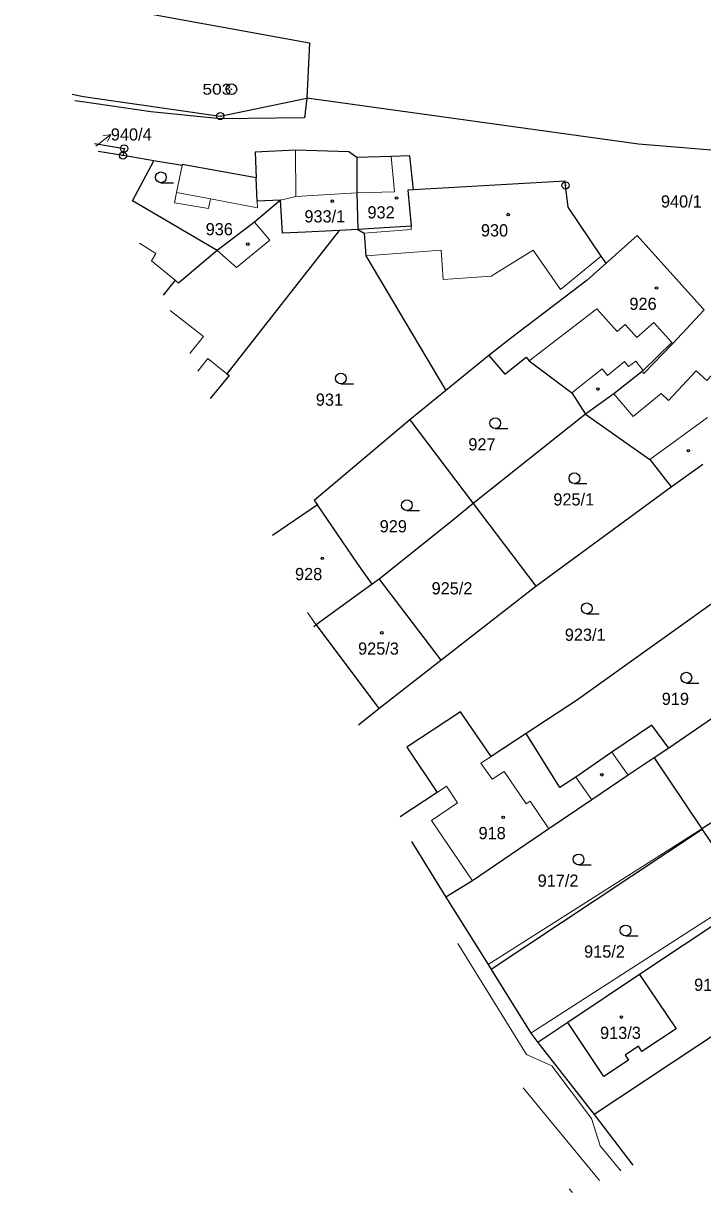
# Model space of a CAD drawing. Extents: x -546984 to -546090, y -1194931 to -1194069.
# Drawn here: x -546957.6 to -546863, y -1194931.4 to -1194768.4 of the extents above; entities that cross this region are included whole.
import ezdxf
from ezdxf.enums import TextEntityAlignment as Align

# ---------------------------------------------------------------- set-up
doc = ezdxf.new("R2010")
doc.units = 0
doc.header["$LTSCALE"] = 0.68
for name, color, linetype, lineweight in [('1', 7, 'Continuous', 25), ('3', 7, 'Continuous', 25), ('4', 7, 'Continuous', 13), ('5', 7, 'Continuous', 25), ('7', 7, 'Continuous', 13), ('8', 7, 'Continuous', 25)]:
    doc.layers.add(name, color=color, linetype=linetype, lineweight=lineweight)
doc.layers.add('2', color=7, linetype='Continuous')

msp = doc.modelspace()

# ---------------------------------------------------------------- linework, layer by layer
at = {"layer": '1'}
for p, q in [((-546911.03, -1194797.1), (-546913.62, -1194797.22)), ((-546892.79, -1194814.67), (-546898.76, -1194819.54)), ((-546867.38, -1194832.99), (-546862.93, -1194829.81)), ((-546886.24, -1194846.83), (-546867.38, -1194832.99)), ((-546916.66, -1194835.51), (-546922.94, -1194839.751)), ((-546908.06, -1194845.85), (-546909.05, -1194846.57)), ((-546908.06, -1194845.85), (-546899.47, -1194857.17)), ((-546899.47, -1194857.17), (-546886.24, -1194846.83)), ((-546916.86, -1194852.24), (-546917.155, -1194852.494)), ((-546916.86, -1194852.24), (-546908.09, -1194863.91)), ((-546908.09, -1194863.91), (-546899.47, -1194857.17)), ((-546910.956, -1194866.15), (-546908.09, -1194863.91)), ((-546869.72, -1194870.76), (-546863.06, -1194880.69)), ((-546863.02, -1194880.74), (-546892.43, -1194900.27)), ((-546903.561, -1194882.442), (-546898.78, -1194890.19)), ((-546856.33, -1194890.73), (-546871.76, -1194900.97)), ((-546871.76, -1194900.97), (-546881.77, -1194907.68)), ((-546881.087, -1194931.397), (-546881.569, -1194930.888))]:
    msp.add_line(p, q, dxfattribs=at)
for points in [[(-546957.649, -1194763.287), (-546946.96, -1194765.76), (-546917.78, -1194771.08), (-546918.16, -1194778.78)], [(-546950.86, -1194778.243), (-546949.25, -1194778.53), (-546930.21, -1194781.27), (-546918.16, -1194778.78)], [(-546918.16, -1194778.78), (-546918.45, -1194781.54), (-546930.19, -1194781.67), (-546939.9, -1194780.68), (-546949.4, -1194779.31), (-546950.459, -1194779.127)], [(-546849.31, -1194790.22), (-546850.76, -1194789.48), (-546856.66, -1194786.46), (-546871.93, -1194785.19), (-546918.16, -1194778.78)], [(-546947.749, -1194785.098), (-546943.6, -1194785.8), (-546943.76, -1194786.79)], [(-546930.66, -1194800.04), (-546942.45, -1194793.09), (-546939.47, -1194787.51), (-546943.76, -1194786.79), (-546947.248, -1194786.201)], [(-546911.18, -1194787.04), (-546912.3, -1194786.28), (-546919.74, -1194786.03), (-546925.32, -1194786.3), (-546925.19, -1194789.89)], [(-546903.26, -1194791.56), (-546903.79, -1194786.8), (-546906.39, -1194786.89), (-546911.18, -1194787.04)], [(-546911.18, -1194787.04), (-546911.18, -1194789.7), (-546911.18, -1194792), (-546911.03, -1194797.1)], [(-546925.19, -1194789.89), (-546935.5, -1194788.03), (-546935.53, -1194788.17), (-546939.47, -1194787.51)], [(-546921.81, -1194793.01), (-546925.07, -1194793.13), (-546925.19, -1194789.89)], [(-546876.44, -1194801.8), (-546877.1, -1194800.82), (-546881.72, -1194793.99), (-546882.08, -1194790.95), (-546882.14, -1194790.36), (-546903.26, -1194791.56)], [(-546903.26, -1194791.56), (-546904.08, -1194791.6), (-546903.61, -1194796.61), (-546911.03, -1194797.1)], [(-546921.81, -1194793.01), (-546925.43, -1194796.05), (-546930.66, -1194800.04)], [(-546913.62, -1194797.22), (-546918.32, -1194797.45), (-546921.52, -1194797.6), (-546921.81, -1194793.01)], [(-546913.62, -1194797.22), (-546929.28, -1194817.2), (-546928.96, -1194817.45), (-546931.598, -1194820.678)], [(-546911.03, -1194797.1), (-546910.17, -1194797.6), (-546909.94, -1194800.75), (-546898.76, -1194819.54)], [(-546862.75, -1194808.31), (-546862.92, -1194808.13), (-546872.08, -1194797.92), (-546876.44, -1194801.8)], [(-546930.66, -1194800.04), (-546936.05, -1194804.59), (-546936.48, -1194804.15), (-546938.156, -1194806.229)], [(-546876.44, -1194801.8), (-546879.08, -1194804.15), (-546889.55, -1194812.17), (-546892.79, -1194814.67)], [(-546862.75, -1194808.31), (-546867.13, -1194812.99), (-546867.26, -1194812.84), (-546871.25, -1194816.74), (-546871.41, -1194816.9), (-546875.33, -1194820), (-546879.29, -1194822.85)], [(-546892.79, -1194814.67), (-546890.53, -1194817.25), (-546887.59, -1194814.88), (-546887.17, -1194815.42), (-546881.2, -1194819.85), (-546879.29, -1194822.85)], [(-546898.76, -1194819.54), (-546903.77, -1194823.63), (-546894.94, -1194835.32)], [(-546879.29, -1194822.85), (-546894.94, -1194835.32), (-546886.24, -1194846.83)], [(-546879.29, -1194822.85), (-546870.34, -1194829.15), (-546867.38, -1194832.99)], [(-546903.77, -1194823.63), (-546917.11, -1194834.86), (-546916.66, -1194835.51)], [(-546909.05, -1194846.57), (-546911.07, -1194843.65), (-546916.66, -1194835.51)], [(-546894.94, -1194835.32), (-546897.87, -1194837.74), (-546908.06, -1194845.85)], [(-546909.05, -1194846.57), (-546911.01, -1194847.99), (-546916.86, -1194852.24)], [(-546858.71, -1194847.16), (-546880.57, -1194862.76), (-546887.59, -1194867.38)], [(-546854.01, -1194860.05), (-546867.66, -1194869.41), (-546869.72, -1194870.76)], [(-546887.59, -1194867.38), (-546892.47, -1194870.59), (-546896.7, -1194864.34), (-546904.18, -1194869.29), (-546899.98, -1194875.6), (-546905.129, -1194878.986)], [(-546867.66, -1194869.41), (-546870.07, -1194866.19), (-546875.64, -1194869.99), (-546880.66, -1194873.46), (-546882.86, -1194874.9), (-546887.59, -1194867.38)], [(-546846.83, -1194870.13), (-546857.16, -1194876.95), (-546863.06, -1194880.69), (-546863.02, -1194880.74), (-546856.92, -1194889.84)], [(-546869.72, -1194870.76), (-546873.37, -1194873.17), (-546878.4, -1194876.64), (-546884.4, -1194880.68), (-546895.07, -1194887.92), (-546898.78, -1194890.19)], [(-546898.78, -1194890.19), (-546892.86, -1194899.57), (-546892.43, -1194900.27)], [(-546892.43, -1194900.27), (-546886.92, -1194909.18), (-546885.92, -1194910.47)], [(-546871.76, -1194900.97), (-546866.65, -1194908.54), (-546871.44, -1194911.7), (-546871.91, -1194910.99), (-546873.78, -1194912.23), (-546873.31, -1194912.94), (-546876.75, -1194915.21), (-546881.77, -1194907.68), (-546885.92, -1194910.47), (-546878.1, -1194920.52)], [(-546849.19, -1194901.37), (-546878.1, -1194920.52), (-546872.7, -1194927.59)]]:
    msp.add_lwpolyline(points, dxfattribs=at)
at = {"layer": '3'}
for p, q in [((-546938.483, -1194790.57), (-546936.733, -1194790.57)), ((-546913.393, -1194818.62), (-546911.643, -1194818.62)), ((-546891.873, -1194824.85), (-546890.123, -1194824.85)), ((-546880.843, -1194832.53), (-546879.093, -1194832.53)), ((-546904.193, -1194836.28), (-546902.443, -1194836.28)), ((-546879.123, -1194850.67), (-546877.373, -1194850.67)), ((-546865.243, -1194860.34), (-546863.493, -1194860.34)), ((-546880.263, -1194885.69), (-546878.513, -1194885.69)), ((-546873.713, -1194895.58), (-546871.963, -1194895.58))]:
    msp.add_line(p, q, dxfattribs=at)
for centre in [(-546938.4829, -1194789.8198), (-546913.3929, -1194817.8698), (-546891.8729, -1194824.0998), (-546880.8429, -1194831.7798), (-546904.1929, -1194835.5298), (-546879.1229, -1194849.9198), (-546865.2429, -1194859.5898), (-546880.2629, -1194884.9398), (-546873.7129, -1194894.8298)]:
    msp.add_circle(centre, 0.75, dxfattribs=at)
at = {"layer": '4'}
for p, q in [((-546919.69, -1194792.49), (-546919.74, -1194786.03)), ((-546905.93, -1194791.84), (-546906.39, -1194786.89)), ((-546936.29, -1194791.94), (-546931.59, -1194792.83)), ((-546919.69, -1194792.49), (-546911.18, -1194792)), ((-546911.18, -1194792), (-546905.93, -1194791.84)), ((-546925.04, -1194794.06), (-546931.59, -1194792.83)), ((-546925.07, -1194793.13), (-546925.04, -1194794.06)), ((-546919.69, -1194792.49), (-546921.81, -1194793.01)), ((-546939.17, -1194800.46), (-546941.446, -1194798.983)), ((-546930.66, -1194800.04), (-546927.93, -1194802.39)), ((-546909.94, -1194800.75), (-546899.4, -1194799.96)), ((-546881.2, -1194819.85), (-546876.96, -1194816.5)), ((-546872.3, -1194815.45), (-546871.25, -1194816.74)), ((-546870.34, -1194829.15), (-546862.28, -1194823.3)), ((-546916.86, -1194852.24), (-546918.06, -1194850.501)), ((-546875.64, -1194869.99), (-546873.37, -1194873.17)), ((-546893.87, -1194871.51), (-546892.47, -1194870.59)), ((-546892.29, -1194873.76), (-546893.87, -1194871.51)), ((-546890.64, -1194872.66), (-546892.29, -1194873.76)), ((-546880.66, -1194873.46), (-546878.4, -1194876.64)), ((-546899.98, -1194875.6), (-546898.67, -1194874.74)), ((-546898.67, -1194874.74), (-546897.16, -1194877.04)), ((-546897.16, -1194877.04), (-546900.77, -1194879.49)), ((-546900.77, -1194879.49), (-546895.07, -1194887.92)), ((-546863.06, -1194880.69), (-546892.86, -1194899.57)), ((-546856.92, -1194889.84), (-546886.92, -1194909.18)), ((-546897.098, -1194896.679), (-546887.51, -1194912.14)), ((-546887.51, -1194912.14), (-546884.01, -1194913.71)), ((-546887.968, -1194916.793), (-546877.351, -1194929.702))]:
    msp.add_line(p, q, dxfattribs=at)
for points in [[(-546931.59, -1194792.83), (-546931.84, -1194794.15), (-546936.57, -1194793.37), (-546936.29, -1194791.94), (-546935.53, -1194788.17)], [(-546927.93, -1194802.39), (-546923.32, -1194798.56), (-546925.43, -1194796.05)], [(-546910.17, -1194797.6), (-546903.58, -1194797.1), (-546903.61, -1194796.61)], [(-546899.4, -1194799.96), (-546899.16, -1194804.08), (-546892.47, -1194803.6)], [(-546892.47, -1194803.6), (-546886.57, -1194799.99), (-546882.8, -1194805.46), (-546877.1, -1194800.82)], [(-546936.48, -1194804.15), (-546939.79, -1194801.46), (-546939.17, -1194800.46)], [(-546934.463, -1194814.365), (-546932.53, -1194812), (-546937.175, -1194808.391)], [(-546872.16, -1194812.13), (-546873.75, -1194810.32), (-546874.9, -1194811.32), (-546877.71, -1194808.17), (-546887.17, -1194815.42)], [(-546867.26, -1194812.84), (-546869.77, -1194810.05), (-546872.16, -1194812.13)], [(-546875.33, -1194820), (-546872.66, -1194823.19), (-546868.74, -1194819.98), (-546867.75, -1194820.92), (-546863.87, -1194816.82), (-546862.39, -1194818.15), (-546856.98, -1194812.37), (-546849.53, -1194818.59)], [(-546871.41, -1194816.9), (-546871.16, -1194817.15), (-546867.13, -1194812.99)], [(-546933.335, -1194816.851), (-546931.92, -1194815.08), (-546929.28, -1194817.2)], [(-546876.96, -1194816.5), (-546876.24, -1194817.45), (-546873.86, -1194815.52), (-546873.3, -1194816.22), (-546872.3, -1194815.45)], [(-546884.4, -1194880.68), (-546887, -1194876.81), (-546887.58, -1194877.16), (-546890.64, -1194872.66)], [(-546884.01, -1194913.71), (-546878.45, -1194921.04), (-546877.27, -1194924.89), (-546874.388, -1194928.357)]]:
    msp.add_lwpolyline(points, dxfattribs=at)
at = {"layer": '5'}
for centre in [(-546914.5968, -1194793.1392), (-546905.6468, -1194792.6992), (-546890.0668, -1194795.0092), (-546926.3768, -1194799.1392), (-546869.3968, -1194805.2492), (-546877.5668, -1194819.3492), (-546864.9568, -1194827.9392), (-546915.9868, -1194842.9392), (-546907.6968, -1194853.3292), (-546877.0268, -1194873.1292), (-546890.7768, -1194879.0592), (-546874.2968, -1194906.9192)]:
    msp.add_circle(centre, 0.175, dxfattribs=at)
at = {"layer": '7'}
msp.add_line((-546945.465, -1194783.832), (-546946.563, -1194784.054), dxfattribs=at)
msp.add_lwpolyline([(-546947.575, -1194785.481), (-546945.465, -1194783.832), (-546945.946, -1194784.844)], dxfattribs=at)
at = {"layer": '8'}
for centre, radius in [((-546928.67, -1194777.5298), 0.75), ((-546928.67, -1194777.5298), 0.03), ((-546930.21, -1194781.2699), 0.5), ((-546930.21, -1194781.2699), 0.0303), ((-546943.6, -1194785.7999), 0.5), ((-546943.76, -1194786.7899), 0.5), ((-546943.76, -1194786.7899), 0.0303), ((-546943.6, -1194785.7999), 0.0303), ((-546882.08, -1194790.9499), 0.5), ((-546882.08, -1194790.9499), 0.0303)]:
    msp.add_circle(centre, radius, dxfattribs=at)

# ---------------------------------------------------------------- texts
at = {"layer": '2'}
for s, p in [('940/4', (-546945.46, -1194784.69)), ('933/1', (-546918.479, -1194796.107)), ('932', (-546909.688, -1194795.552)), ('936', (-546932.24, -1194797.9)), ('925/1', (-546883.78, -1194835.58)), ('925/2', (-546900.75, -1194847.98)), ('923/1', (-546882.18, -1194854.45)), ('925/3', (-546911, -1194856.38)), ('913/3', (-546877.27, -1194909.97))]:
    msp.add_text(s, height=1.7, dxfattribs=at).set_placement(p)
for s, p in [('940/1', (-546865.938, -1194794.028)), ('930', (-546891.979, -1194798.06)), ('926', (-546871.279, -1194808.3)), ('931', (-546914.989, -1194821.67)), ('927', (-546893.729, -1194827.9)), ('929', (-546906.089, -1194839.33)), ('928', (-546917.889, -1194845.99)), ('919', (-546866.769, -1194863.39)), ('918', (-546892.309, -1194882.11)), ('917/2', (-546883.12, -1194888.74)), ('915/2', (-546876.65, -1194898.63)), ('913/2', (-546861.31, -1194903.26))]:
    msp.add_text(s, height=1.7, dxfattribs=at).set_placement(p, align=Align.CENTER)
at = {"layer": '8', "width": 1.2}
msp.add_text('503', height=1.5, dxfattribs=at).set_placement((-546928.67, -1194778.28), align=Align.RIGHT)

doc.saveas('drawing.dxf')
